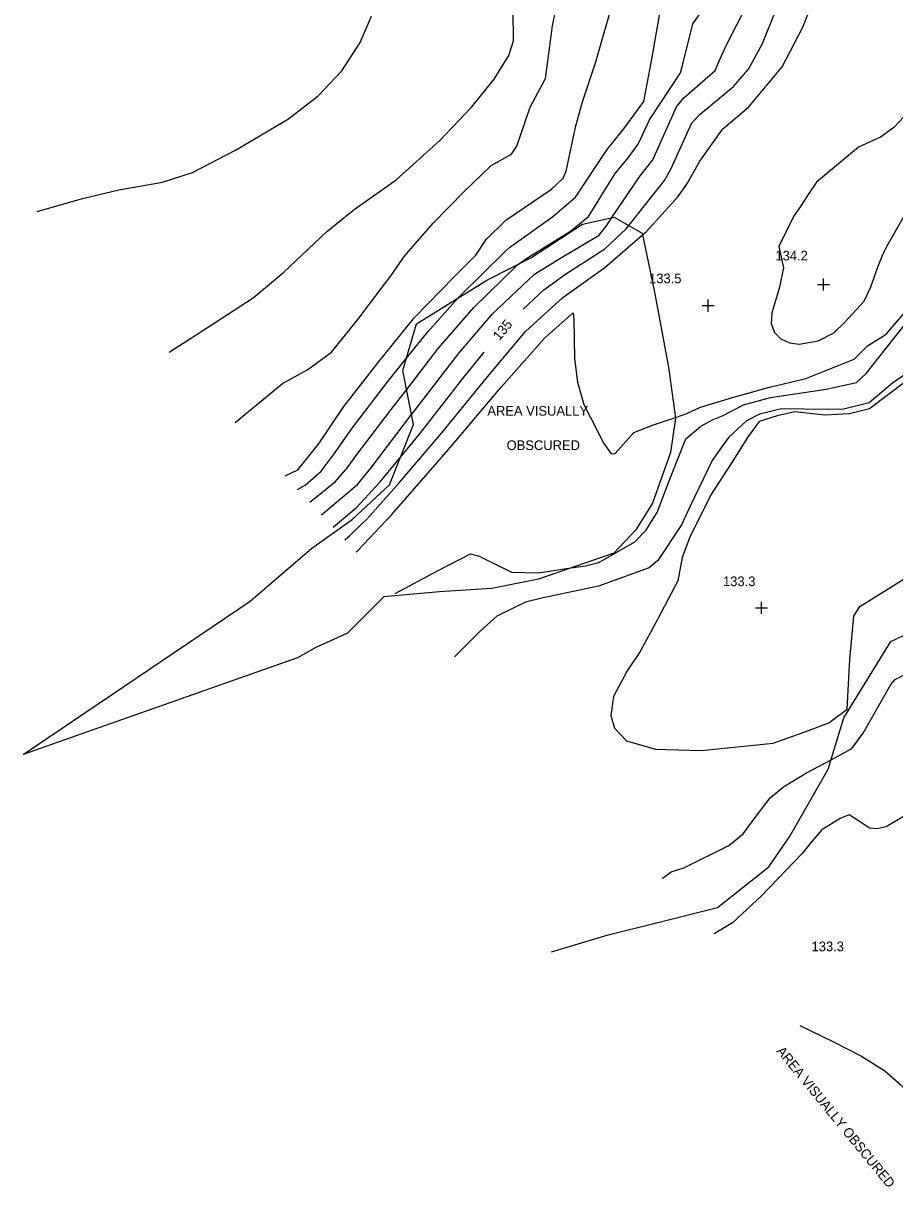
# Model space of a CAD drawing. Extents: x 1475150 to 2003689, y 770235 to 1112803.
# Drawn here: x 2000706.1 to 2000886.2, y 772929.2 to 773169.6 of the extents above; entities that cross this region are included whole.
import ezdxf

# ---------------------------------------------------------------- set-up
doc = ezdxf.new("R2010")
doc.units = 0
for name, color, linetype in [('RD_DTM_Major1', 7, 'Continuous'), ('RD_DTM_Major1_Lbl', 7, 'Continuous'), ('RD_DTM_Major2', 7, 'Continuous'), ('RD_DTM_Minor1', 7, 'Continuous'), ('RD_DTM_Minor2', 7, 'Continuous'), ('RD_DTM_Obscure', 7, 'Continuous'), ('RD_DTM_Spot_Elev', 7, 'Continuous'), ('RD_TX_Misc1', 7, 'Continuous')]:
    doc.layers.add(name, color=color, linetype=linetype)

msp = doc.modelspace()

# ---------------------------------------------------------------- linework, layer by layer
at = {"layer": 'RD_DTM_Major1'}
for points in [[(2000749.92, 773087.08), (2000759.67, 773095.17), (2000764.93, 773098.03), (2000769.84, 773101.66), (2000775.26, 773108.36), (2000782.53, 773117.99), (2000784.84, 773121.38), (2000790.81, 773128.31), (2000797.26, 773134.85), (2000802.83, 773140.25), (2000807.05, 773142.59), (2000808.14, 773144.18), (2000810.86, 773152.3), (2000814.02, 773158.18), (2000815.49, 773169.08), (2000817.33, 773178.24), (2000817.09, 773182.95), (2000815.65, 773188.04), (2000810.56, 773199.84), (2000809.76, 773202.89), (2000807.32, 773207), (2000799.61, 773217.16), (2000799.38, 773217.54)], [(2000831.27, 773127.82), (2000838.62, 773137.14), (2000839.95, 773139.49), (2000844.29, 773149.02), (2000846.07, 773150.91), (2000852.87, 773156.52), (2000855.96, 773160.09), (2000858.92, 773165.4), (2000861.54, 773172.12)], [(2000770.15, 773065.48), (2000775, 773069.57), (2000779.87, 773074.87), (2000784.14, 773080.03)]]:
    msp.add_lwpolyline(points, dxfattribs=at)
at = {"layer": 'RD_DTM_Major2'}
for points in [[(2000809.46, 773110.51), (2000813.68, 773114.52), (2000818.19, 773117.77), (2000826.33, 773122.99), (2000830.74, 773127.15), (2000831.27, 773127.82)], [(2000784.14, 773080.03), (2000788.28, 773085.05), (2000796.97, 773096.23), (2000801.38, 773101.62)]]:
    msp.add_lwpolyline(points, dxfattribs=at)
at = {"layer": 'RD_DTM_Minor1'}
for points in [[(2000760.23, 773076.08), (2000762.9, 773077.32), (2000767.12, 773082.63), (2000772.38, 773090.4), (2000779.5, 773099.53), (2000786.97, 773108.79), (2000795.15, 773117.24), (2000799.62, 773121.7), (2000801.76, 773124.91), (2000805.85, 773128.95), (2000815.32, 773135.34), (2000817.72, 773137.63), (2000818.33, 773139.07), (2000820.31, 773148.39), (2000821.71, 773153.39), (2000824.42, 773161.64), (2000828.24, 773174.93)], [(2000796.01, 773112.87), (2000796.59, 773113.52), (2000805.62, 773122.4), (2000806.62, 773123.3), (2000815.55, 773129.66), (2000820.26, 773133.66), (2000826.78, 773143.49), (2000830.21, 773147.81), (2000834.39, 773153.41), (2000835.89, 773161.45), (2000838.06, 773173.95)], [(2000709.03, 773130.74), (2000718.4, 773133.38), (2000725.89, 773135.19), (2000734.88, 773136.74), (2000741.11, 773138.74), (2000749.99, 773143.37), (2000760.91, 773149.89), (2000767.06, 773154.59), (2000771.95, 773159.81), (2000775.77, 773165.63), (2000778.12, 773171.08)], [(2000736.26, 773101.67), (2000741.84, 773105.2), (2000753.63, 773112.86), (2000760, 773118.15), (2000768.8, 773126.51), (2000774.52, 773131.1), (2000783.18, 773137.23), (2000792.23, 773145.38), (2000798.82, 773152.33), (2000803.41, 773158.03), (2000806.48, 773162.92), (2000807.4, 773165.95), (2000807.39, 773172.23)], [(2000808.55, 773119.87), (2000810.54, 773121.25), (2000819.24, 773126.64), (2000822.91, 773129.71), (2000828.46, 773138.56), (2000831.13, 773141.8), (2000833.18, 773144.62), (2000835.53, 773149.66), (2000841.97, 773159.37), (2000842.47, 773161.41), (2000844.49, 773169.47), (2000846.02, 773171.61)], [(2000827.78, 773129.47), (2000833.58, 773138.07), (2000836.23, 773141.38), (2000841.14, 773152.31), (2000842.66, 773154.17), (2000849.12, 773159.86), (2000850.05, 773162.1), (2000851.53, 773165.3), (2000854.72, 773171.56)], [(2000834.12, 773125.89), (2000834.83, 773126.51), (2000841.4, 773133.72), (2000843.24, 773136.36), (2000845.93, 773141.11), (2000850.67, 773147.77), (2000853.71, 773150.34), (2000856.08, 773152.31), (2000862.97, 773160.59), (2000867.25, 773168.77), (2000868.66, 773172.43)], [(2000840.91, 773088.17), (2000843.26, 773088.95), (2000846.1, 773090.25), (2000852.68, 773092.31), (2000860.31, 773094.4), (2000867.81, 773096.19), (2000877.81, 773100.19), (2000880.59, 773102.94), (2000884.47, 773105.34), (2000889.54, 773111.32), (2000891.41, 773114.85), (2000892.2, 773118.4), (2000892.86, 773122.32), (2000896.23, 773132.89), (2000899.53, 773142.13), (2000899.47, 773147.97), (2000900.28, 773150.74), (2000901.15, 773150.96), (2000904.74, 773150.32), (2000906.27, 773149.12), (2000908.8, 773148.42), (2000919.01, 773147.76), (2000925.91, 773144.68), (2000926.61, 773143.96)], [(2000889.11, 773151.37), (2000886.04, 773148.06), (2000883.24, 773146.06), (2000878.72, 773143.98), (2000870.02, 773136.79), (2000868.49, 773134.46), (2000866.87, 773131.94), (2000865.32, 773129.67), (2000862.26, 773123.49), (2000863.25, 773119.04), (2000862.33, 773114.78), (2000860.82, 773109.76), (2000860.7, 773107.51), (2000861.36, 773105.72), (2000862.7, 773104.4), (2000864.47, 773103.59), (2000866.47, 773103.27), (2000870.41, 773103.96), (2000873.66, 773105.62), (2000875.87, 773107.81), (2000879.89, 773112.18), (2000881.29, 773115.16), (2000882.78, 773119.4)], [(2000882.78, 773119.4), (2000883.74, 773121.8), (2000884.62, 773123.59), (2000889.05, 773131.32)], [(2000819.27, 773057.05), (2000822.33, 773057.51), (2000825.1, 773058.21), (2000832.5, 773062.47), (2000834.76, 773064.82), (2000837.13, 773068.53), (2000839.58, 773075.09), (2000843.03, 773083.71), (2000846.11, 773086.38), (2000848.68, 773087.73), (2000850.78, 773088.56), (2000854.94, 773090.77), (2000860.57, 773092.28), (2000872.05, 773094.03), (2000878.31, 773095.36), (2000880.34, 773097.22), (2000888.08, 773107.06)], [(2000762.83, 773073.3), (2000764.38, 773074.18), (2000767.66, 773077.05), (2000770.41, 773080.67), (2000774.13, 773085.97), (2000781.5, 773095.61), (2000785.32, 773100.37)], [(2000888.65, 773097.27), (2000885.76, 773095.24), (2000880.95, 773091.18), (2000875.65, 773089.87), (2000872.4, 773089.81), (2000862.79, 773089.94), (2000858.28, 773088.84), (2000855.55, 773087.43), (2000851.93, 773084.08), (2000850.09, 773081.54), (2000848.48, 773079.29), (2000843.91, 773069.8), (2000842.12, 773065.99), (2000837.23, 773058.58), (2000835.44, 773057.11), (2000824.98, 773053.26), (2000813.57, 773050.89), (2000809.88, 773050), (2000804.01, 773047.12), (2000800.46, 773043.91), (2000795.24, 773038.69)], [(2000765.34, 773070.62), (2000770.65, 773074.94), (2000773.17, 773077.87), (2000774.95, 773080.32), (2000782.16, 773089.78), (2000785.36, 773093.93)], [(2000888.56, 773095.67), (2000880.98, 773089.94), (2000876.84, 773088.93), (2000871.77, 773088.65), (2000865.6, 773089.33), (2000861.89, 773088.46), (2000858.21, 773087.35), (2000855.93, 773084.2), (2000852.43, 773078.61), (2000848.24, 773072.14), (2000843.87, 773063.39), (2000842.29, 773059.2), (2000841.4, 773054.36), (2000837.23, 773046.54), (2000833.64, 773039.77), (2000830.91, 773035.83), (2000828.1, 773030.52), (2000827.52, 773026.57), (2000828.27, 773023.93), (2000830.79, 773021.33), (2000836.79, 773019.58), (2000846.3, 773019.33), (2000861.06, 773020.83), (2000867.32, 773023.08), (2000872.57, 773025.08), (2000876.35, 773027.9), (2000876.93, 773038.14), (2000877.75, 773047.06), (2000879.01, 773049.09), (2000889.29, 773055.5)], [(2000767.74, 773068.06), (2000775.19, 773074.33), (2000777.92, 773077.67), (2000786.37, 773088.74)], [(2000838.16, 772992.87), (2000840.01, 772994.24), (2000842.62, 772995.08), (2000851.9, 772999.67), (2000854.86, 773002.1), (2000857.56, 773005.79), (2000860.45, 773009.58), (2000863.21, 773011.86), (2000867.95, 773014.7), (2000873.08, 773017.44)]]:
    msp.add_lwpolyline(points, dxfattribs=at)
at = {"layer": 'RD_DTM_Minor2'}
for points in [[(2000786.37, 773088.74), (2000786.51, 773088.92), (2000796.21, 773101.54), (2000803.17, 773109.6), (2000811.78, 773117.77), (2000817, 773121), (2000825.12, 773125.83), (2000826.64, 773127.78), (2000827.78, 773129.47)], [(2000772.58, 773062.89), (2000773.7, 773063.8), (2000777.18, 773067.18), (2000783.84, 773074.62), (2000792.61, 773084.95), (2000802.04, 773096.52), (2000809.91, 773105.9), (2000817.64, 773112.96), (2000826.33, 773119.14), (2000834.12, 773125.89)], [(2000785.36, 773093.93), (2000791.89, 773102.38), (2000799.23, 773110.87), (2000808.19, 773119.62), (2000808.55, 773119.87)], [(2000785.32, 773100.37), (2000789.7, 773105.82), (2000796.01, 773112.87)], [(2000774.93, 773060.38), (2000775.28, 773060.69), (2000782.32, 773068.12), (2000793.98, 773081.55), (2000804.86, 773094.41), (2000813.9, 773104.63), (2000819.79, 773109.8), (2000819.88, 773108.44), (2000820.06, 773100.33), (2000820.67, 773095.42), (2000822, 773090.81), (2000826.11, 773082.74), (2000827.6, 773080.61), (2000828.44, 773080.69), (2000832.29, 773085.05), (2000836.35, 773086.65), (2000840.91, 773088.17)], [(2000783.01, 773051.76), (2000791.72, 773056.43), (2000798.56, 773059.96), (2000800.22, 773059.57), (2000807.04, 773056.21), (2000812.57, 773056.04), (2000819.27, 773057.05)], [(2000873.08, 773017.44), (2000877.38, 773019.74), (2000879.68, 773022.94), (2000885.41, 773032.99), (2000886.27, 773034), (2000891.27, 773036.53), (2000895.1, 773037.84), (2000900.15, 773038.45), (2000905.13, 773038.33), (2000907.94, 773039.5), (2000909.82, 773041.24), (2000911.15, 773043.55), (2000911.56, 773045.58), (2000911.34, 773046.73)], [(2000888.34, 773005.89), (2000884.46, 773003.58), (2000882.58, 773003.12), (2000881, 773003.31), (2000878.7, 773004.78), (2000876.79, 773006.05), (2000874.94, 773005.28), (2000871.12, 773002.94), (2000869.04, 773000.49), (2000867.09, 772998.08), (2000858.7, 772989.31), (2000852.71, 772983.75), (2000848.88, 772981.43)], [(2000866.6, 772962.5), (2000873.58, 772959.15), (2000879.32, 772956.17), (2000884.15, 772953.15), (2000887.56, 772950.18), (2000893.57, 772943.52), (2000895.91, 772942.6), (2000902.12, 772941.28), (2000905.87, 772939.86), (2000910.94, 772936.68)]]:
    msp.add_lwpolyline(points, dxfattribs=at)
at = {"layer": 'RD_DTM_Obscure'}
for points in [[(2000752.99, 773050.19), (2000765.73, 773061.14), (2000774.08, 773067.04), (2000781.84, 773074.26), (2000786.78, 773086.67), (2000784.6, 773097.85), (2000787.37, 773107.49), (2000801.91, 773116.54), (2000811.03, 773121.12), (2000821.71, 773128.12), (2000828.26, 773129.57), (2000834.05, 773126.21), (2000836.55, 773114.01), (2000839.49, 773098.56), (2000840.93, 773088), (2000839.91, 773080.94), (2000836.19, 773070.47), (2000832.74, 773064.96), (2000828.17, 773060.13), (2000812.61, 773054.75), (2000802.98, 773052.84), (2000792.16, 773052.09), (2000780.65, 773051.1), (2000773.13, 773043.55), (2000766.56, 773040.63), (2000762.78, 773038.47), (2000706.13, 773018.54), (2000752.99, 773050.19)], [(2000815.27, 772977.76), (2000826.98, 772981.27), (2000836.74, 772983.67), (2000849.6, 772986.9), (2000860.2, 772995.29), (2000864.48, 773001.51), (2000872.47, 773015.46), (2000875.72, 773026.06), (2000885.41, 773041.85), (2000893.52, 773045.73)]]:
    msp.add_lwpolyline(points, dxfattribs=at)
at = {"layer": 'RD_DTM_Spot_Elev'}
for p, q in [((2000870.23, 773115.62), (2000872.73, 773115.62)), ((2000871.48, 773114.37), (2000871.48, 773116.87)), ((2000846.39, 773111.26), (2000848.89, 773111.26)), ((2000847.64, 773110.01), (2000847.64, 773112.51)), ((2000857.42, 773048.81), (2000859.92, 773048.81)), ((2000858.67, 773047.56), (2000858.67, 773050.06))]:
    msp.add_line(p, q, dxfattribs=at)

# ---------------------------------------------------------------- texts
at = {"layer": 'RD_DTM_Major1_Lbl'}
msp.add_text('135', height=2, rotation=50.7056, dxfattribs=at).set_placement((2000804.53, 773103.89))
at = {"layer": 'RD_DTM_Spot_Elev'}
for s, p in [('134.2', (2000861.56, 773120.6)), ('133.5', (2000835.45, 773115.88)), ('133.3', (2000850.73, 773053.3)), ('133.3', (2000869.02, 772977.86))]:
    msp.add_text(s, height=2, dxfattribs=at).set_placement(p)
at = {"layer": 'RD_TX_Misc1'}
for s, p in [('AREA VISUALLY', (2000802.03, 773088.53)), ('OBSCURED', (2000806.01, 773081.42))]:
    msp.add_text(s, height=2, dxfattribs=at).set_placement(p)
msp.add_text('AREA VISUALLY OBSCURED', height=2, rotation=309.2594, dxfattribs=at).set_placement((2000861.66, 772957.19))

doc.saveas('drawing.dxf')
